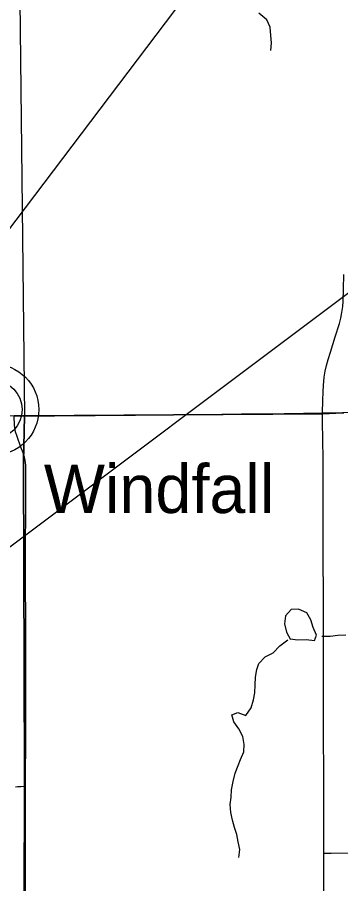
# Model space of a CAD drawing. Extents: x 0 to 34, y 0 to 22.
# Drawn here: x 6.734 to 6.998, y 15.26 to 15.966 of the extents above; entities that cross this region are included whole.
import ezdxf

# ---------------------------------------------------------------- set-up
doc = ezdxf.new("R2010")
doc.units = 0
for name, color, linetype in [('GM_X_County_Road', 7, 'Continuous'), ('GM_X_Minor_Lake', 7, 'Continuous'), ('GM_X_Minor_River', 7, 'Continuous'), ('GM_X_Rail_Line_Text', 7, 'Continuous'), ('GM_X_State_Route', 7, 'Continuous'), ('GM_X_Township', 7, 'Continuous'), ('GM_X_Township_Road', 7, 'Continuous'), ('GM_X_Unincorporated', 7, 'Continuous'), ('GM_X_Unincorporated_Text', 7, 'Continuous'), ('SH_Text', 7, 'Continuous')]:
    doc.layers.add(name, color=color, linetype=linetype)

msp = doc.modelspace()

# ---------------------------------------------------------------- linework, layer by layer
at = {"layer": 'GM_X_County_Road'}
msp.add_lwpolyline([(6.74086, 15.12664), (6.7409, 15.14919), (6.74086, 15.20128), (6.74073, 15.25553), (6.74077, 15.33951), (6.74098, 15.38369), (6.74104, 15.47237), (6.74087, 15.50739), (6.74098, 15.59158), (6.7409, 15.60127), (6.7405, 15.60514), (6.74, 15.60791), (6.7389, 15.61142), (6.73708, 15.61604), (6.73407, 15.62478), (6.73268, 15.62838), (6.7318, 15.6339), (6.7315, 15.64118)], dxfattribs=at)
at = {"layer": 'GM_X_Minor_Lake'}
for points in [[(6.97628, 15.45825), (6.9781, 15.46265), (6.97534, 15.46886), (6.97334, 15.47509), (6.97021, 15.48092), (6.96335, 15.48402), (6.9573, 15.48373), (6.95266, 15.47852), (6.95202, 15.47206), (6.95346, 15.46525), (6.95648, 15.45979)], [(6.97628, 15.45825), (6.9781, 15.46265), (6.97534, 15.46886), (6.97334, 15.47509), (6.97021, 15.48092), (6.96335, 15.48402), (6.9573, 15.48373), (6.95266, 15.47852), (6.95202, 15.47206), (6.95346, 15.46525), (6.95678, 15.45924)], [(6.9564, 15.4598), (6.96284, 15.45897), (6.96965, 15.45909), (6.97628, 15.45825)], [(6.95648, 15.45979), (6.96284, 15.45897), (6.96965, 15.45909), (6.97628, 15.45825)]]:
    msp.add_lwpolyline(points, dxfattribs=at)
at = {"layer": 'GM_X_Minor_River'}
for points in [[(6.94078, 15.93919), (6.94124, 15.94546), (6.94076, 15.95152), (6.94026, 15.95834), (6.93751, 15.96437), (6.93098, 15.96975)], [(7.00192, 15.46269), (6.9955, 15.46238), (6.98909, 15.46151), (6.98246, 15.46159)], [(6.91471, 15.28148), (6.91535, 15.28813), (6.9141, 15.29437), (6.91305, 15.30023), (6.91125, 15.30589), (6.90963, 15.31194), (6.90801, 15.31817), (6.90752, 15.32461), (6.90836, 15.3307), (6.90863, 15.33677), (6.91003, 15.34344), (6.91161, 15.35011), (6.91414, 15.3566), (6.91614, 15.36138), (6.91868, 15.3675), (6.91914, 15.37358), (6.91789, 15.3802), (6.91475, 15.3864), (6.91049, 15.39202), (6.90907, 15.39788), (6.91395, 15.39967), (6.92042, 15.39732), (6.92467, 15.40346), (6.92663, 15.40995), (6.92767, 15.41585), (6.92793, 15.42212), (6.9282, 15.42857), (6.92941, 15.43485), (6.93103, 15.43963), (6.93623, 15.44503), (6.9426, 15.44837), (6.94799, 15.45415), (6.95452, 15.45901)]]:
    msp.add_lwpolyline(points, dxfattribs=at)
at = {"layer": 'GM_X_Rail_Line_Text'}
for points in [[(7.25546, 17.90618), (6.96766, 17.90085), (6.9468, 17.90052), (6.71961, 17.89693), (6.72194, 17.73847), (6.72576, 17.34372), (6.73112, 16.77245), (6.7311, 16.53864), (6.73111, 16.53754), (6.73161, 16.49675), (6.73164, 16.49443), (6.7317, 16.48075), (6.73239, 16.31915), (6.74001, 15.64147), (6.98283, 15.64326), (6.99923, 15.64397)], [(6.74627, 14.37116), (6.74201, 15.01654), (6.74144, 15.02092), (6.73934, 15.12764), (6.74001, 15.34907), (6.73918, 15.60382), (6.74001, 15.64147), (6.73142, 15.64139), (6.61338, 15.64137), (6.52036, 15.64103), (6.49563, 15.64107), (6.48595, 15.64093), (6.45516, 15.64069), (6.41795, 15.64046), (6.33251, 15.63938), (6.29968, 15.63934), (6.24955, 15.63838), (6.24231, 15.63821), (6.14973, 15.63585), (6.04406, 15.63962), (6.04095, 15.63985), (5.15815, 15.63216)]]:
    msp.add_lwpolyline(points, dxfattribs=at)
msp.add_lwpolyline([(6.7466, 14.1), (8.9, 14.1), (8.9, 15.65232), (8.85084, 15.65219), (8.81714, 15.6521), (8.55432, 15.65138), (8.38107, 15.65063), (8.0395, 15.64944), (7.56787, 15.64626), (7.49589, 15.64556), (7.47838, 15.64609), (7.17478, 15.64453), (6.99923, 15.64397), (6.98283, 15.64326), (6.74001, 15.64147), (6.73918, 15.60382), (6.74001, 15.34907), (6.73934, 15.12764), (6.74144, 15.02092), (6.74201, 15.01654), (6.74627, 14.37116), (6.74627, 14.36613)], close=True, dxfattribs=at)
at = {"layer": 'GM_X_State_Route'}
for points in [[(6.7315, 15.64118), (6.83031, 15.6421), (6.87367, 15.64258), (6.90074, 15.64288), (6.91677, 15.64305), (6.93741, 15.64326), (6.95154, 15.6434), (6.98289, 15.64388)], [(6.98289, 15.64388), (7.00025, 15.64396)]]:
    msp.add_lwpolyline(points, dxfattribs=at)
at = {"layer": 'GM_X_Township'}
msp.add_lwpolyline([(6.72576, 17.34372), (6.73112, 16.77245), (6.7311, 16.53864), (6.73111, 16.53754), (6.73161, 16.49675), (6.73164, 16.49443), (6.7317, 16.48075), (6.73239, 16.31915), (6.74001, 15.64147), (6.73142, 15.64139), (6.61338, 15.64137), (6.52036, 15.64103), (6.49563, 15.64107), (6.48595, 15.64093), (6.45516, 15.64069), (6.41795, 15.64046), (6.33251, 15.63938), (6.29968, 15.63934), (6.24955, 15.63838), (6.24231, 15.63821), (6.14973, 15.63585), (6.04406, 15.63962), (6.04095, 15.63985), (5.15815, 15.63216)], dxfattribs=at)
at = {"layer": 'GM_X_Township_Road'}
for points in [[(6.98289, 15.64388), (6.98305, 15.65392), (6.98331, 15.66119), (6.98357, 15.66622), (6.98432, 15.67305), (6.98512, 15.67804), (6.98611, 15.68262), (6.98741, 15.68737), (6.98929, 15.69352), (6.9933, 15.70604), (6.99681, 15.71691), (6.99782, 15.72107), (6.99875, 15.72585), (6.99937, 15.7306), (6.99967, 15.73477), (7.00012, 15.74478), (7.00023, 15.75684)], [(6.98297, 15.63403), (6.98291, 15.63802), (6.98289, 15.64388)], [(6.98395, 15.25188), (6.98398, 15.27606), (6.98405, 15.28499), (6.98392, 15.30222), (6.98403, 15.31639), (6.98392, 15.33133), (6.98371, 15.39962), (6.98375, 15.41444), (6.98362, 15.43625), (6.98372, 15.45497), (6.98358, 15.50171), (6.98349, 15.51936), (6.9834, 15.53214), (6.98333, 15.60361), (6.98311, 15.62455), (6.98297, 15.63403)], [(6.73269, 15.33904), (6.73452, 15.33935), (6.73684, 15.33949), (6.74077, 15.33951)], [(6.98405, 15.28499), (6.99007, 15.28512), (7.00478, 15.28531)]]:
    msp.add_lwpolyline(points, dxfattribs=at)
at = {"layer": 'GM_X_Unincorporated'}
for radius in [0.0372, 0.02358]:
    msp.add_circle((6.71446, 15.64663), radius, dxfattribs=at)
at = {"layer": 'SH_Text'}
msp.add_lwpolyline([(7.05444, 15.77941), (6.27322, 15.19343), (7.05444, 16.22573)], close=True, dxfattribs=at)

# ---------------------------------------------------------------- texts
at = {"layer": 'GM_X_Unincorporated_Text'}
msp.add_text('Windfall', height=0.039489, rotation=0.00001, dxfattribs=at).set_placement((6.7557, 15.56227))

doc.saveas('drawing.dxf')
